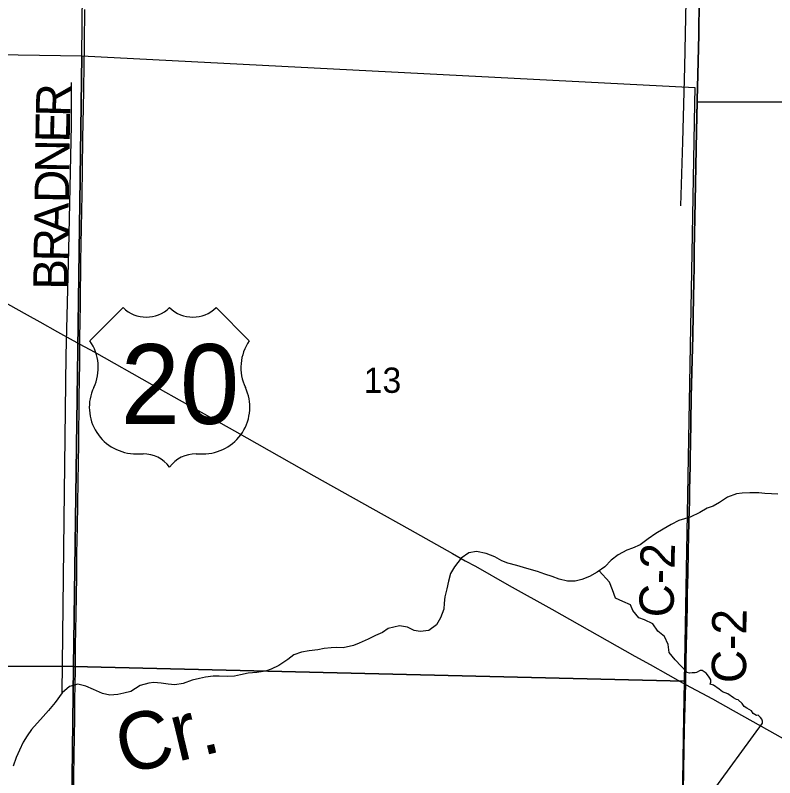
# Model space of a CAD drawing. Extents: x 0 to 34, y 0 to 22.
# Drawn here: x 6.42 to 7.676, y 18.874 to 20.135 of the extents above; entities that cross this region are included whole.
import ezdxf

# ---------------------------------------------------------------- set-up
doc = ezdxf.new("R2010")
doc.units = 0
for name, color, linetype in [('GM_X_City_Street', 7, 'Continuous'), ('GM_X_County_Road', 7, 'Continuous'), ('GM_X_County_Road_Text', 7, 'Continuous'), ('GM_X_Major_River', 7, 'Continuous'), ('GM_X_Major_River_Text', 7, 'Continuous'), ('GM_X_Minor_River', 7, 'Continuous'), ('GM_X_Section', 7, 'Continuous'), ('GM_X_Section_Text', 7, 'Continuous'), ('GM_X_Township_Road', 7, 'Continuous'), ('GM_X_Township_Road_Text', 7, 'Continuous'), ('GM_X_US_Location', 7, 'Continuous'), ('GM_X_US_Route', 7, 'Continuous'), ('GM_X_US_Shield', 7, 'Continuous'), ('SH_Cut_Line', 7, 'Continuous')]:
    doc.layers.add(name, color=color, linetype=linetype)

msp = doc.modelspace()

# ---------------------------------------------------------------- linework, layer by layer
at = {"layer": 'GM_X_City_Street'}
msp.add_lwpolyline([(6.5392, 20.9), (5.527, 20.9), (5.5144, 20.0832), (6.5307, 20.0674)], close=True, dxfattribs=at)
at = {"layer": 'GM_X_County_Road'}
for points in [[(7.5482, 19.9914), (7.5483, 19.9933), (7.5491, 20.0362), (7.5506, 20.1015), (7.5514, 20.1605), (7.5521, 20.1904), (7.5528, 20.2173), (7.5543, 20.2911), (7.5548, 20.3278), (7.556, 20.3619), (7.5564, 20.3806), (7.5567, 20.4036), (7.5571, 20.4228), (7.5579, 20.4589), (7.5585, 20.4894), (7.559, 20.516)], [(7.5287, 19.0281), (7.5295, 19.0663), (7.5299, 19.0908), (7.5305, 19.1119), (7.5312, 19.1349), (7.5315, 19.1554), (7.5318, 19.1772), (7.5324, 19.2101), (7.5332, 19.2474), (7.5337, 19.2735), (7.5342, 19.2944), (7.5347, 19.3177), (7.5351, 19.327), (7.5353, 19.3363), (7.5355, 19.3489), (7.5362, 19.3891), (7.5364, 19.4034), (7.5368, 19.4258), (7.5377, 19.4606), (7.5385, 19.5035), (7.5394, 19.5445), (7.5407, 19.6035), (7.5417, 19.639), (7.5426, 19.6937), (7.543, 19.7167), (7.5433, 19.7453), (7.5435, 19.772), (7.5448, 19.8261), (7.5472, 19.9423), (7.5482, 19.9914)]]:
    msp.add_lwpolyline(points, dxfattribs=at)
at = {"layer": 'GM_X_Major_River'}
for points in [[(7.6813, 19.3427), (7.6707, 19.3431), (7.6597, 19.344), (7.6499, 19.3448), (7.6351, 19.3449), (7.6222, 19.3442), (7.6127, 19.3432), (7.5982, 19.338), (7.5845, 19.329), (7.5742, 19.3226), (7.5643, 19.3193), (7.5521, 19.3122), (7.536, 19.3044)], [(7.536, 19.3044), (7.5177, 19.299), (7.5047, 19.2924), (7.4916, 19.2848), (7.4797, 19.2775), (7.467, 19.2691), (7.4538, 19.2591), (7.4412, 19.2534), (7.4313, 19.2502), (7.4175, 19.2426), (7.4055, 19.2335), (7.395, 19.2226), (7.3827, 19.2138), (7.37, 19.2065), (7.357, 19.2015), (7.3463, 19.1991), (7.3334, 19.1991), (7.3195, 19.2024), (7.3082, 19.2065), (7.2962, 19.2106), (7.2838, 19.2151), (7.2703, 19.2188), (7.2605, 19.2213), (7.2496, 19.2246), (7.235, 19.2288), (7.2248, 19.2324), (7.2132, 19.2392), (7.199, 19.2444), (7.1828, 19.2479), (7.1702, 19.2455), (7.1575, 19.2371), (7.1469, 19.2226), (7.1402, 19.2113), (7.1365, 19.1989), (7.1339, 19.1861), (7.1309, 19.1728), (7.1295, 19.1626), (7.1289, 19.1528), (7.1233, 19.1385), (7.1169, 19.1269), (7.1042, 19.1173), (7.0901, 19.1154), (7.0799, 19.1172), (7.0691, 19.1227), (7.0555, 19.125), (7.0372, 19.1205), (7.0276, 19.1142), (7.0161, 19.1088), (7.004, 19.1028), (6.9893, 19.0966), (6.9797, 19.0926), (6.9626, 19.0889), (6.952, 19.0891), (6.9425, 19.0886), (6.9311, 19.0874), (6.9209, 19.0853), (6.9064, 19.0834), (6.8939, 19.0814), (6.8813, 19.0768), (6.8709, 19.0695), (6.8562, 19.0596), (6.8437, 19.0532), (6.834, 19.0503), (6.8196, 19.0479), (6.8055, 19.0468), (6.7926, 19.0441), (6.7827, 19.042), (6.7713, 19.0411), (6.7577, 19.0419), (6.7475, 19.0417), (6.7349, 19.0401), (6.725, 19.0381), (6.7128, 19.035), (6.6979, 19.0296), (6.6843, 19.0277), (6.6733, 19.0287), (6.6616, 19.0301), (6.6496, 19.0312), (6.6411, 19.0303), (6.627, 19.0264), (6.6116, 19.0166), (6.5998, 19.0138), (6.5899, 19.0114), (6.577, 19.0106), (6.5646, 19.0131), (6.5496, 19.0196), (6.5373, 19.0252), (6.5241, 19.0286), (6.51, 19.0247), (6.4982, 19.0142), (6.4862, 18.9984), (6.4753, 18.985), (6.4667, 18.9753), (6.4472, 18.9538), (6.4402, 18.9433), (6.4335, 18.9328), (6.4275, 18.9197), (6.4222, 18.9073), (6.417, 18.893)]]:
    msp.add_lwpolyline(points, dxfattribs=at)
at = {"layer": 'GM_X_Minor_River'}
msp.add_line((7.5282, 18.7894), (7.656, 18.9638), dxfattribs=at)
for points in [[(7.5437, 20.9), (7.5419, 20.8536), (7.5371, 20.7342), (7.5355, 20.6109), (7.5328, 20.4994), (7.5329, 20.3973), (7.5305, 20.3017), (7.5295, 20.186), (7.5269, 20.0494), (7.5234, 19.925), (7.5204, 19.8192)], [(6.4982, 19.0142), (6.5013, 19.3001), (6.5046, 19.5721), (6.5093, 19.7466), (6.5137, 19.9529), (6.5136, 20.0231)], [(7.5312, 19.0481), (7.5116, 19.0687), (7.5013, 19.0811), (7.5001, 19.0941), (7.494, 19.1071), (7.4829, 19.1161), (7.4745, 19.1285), (7.461, 19.1349), (7.4512, 19.1385), (7.4417, 19.1501), (7.4374, 19.1597), (7.425, 19.165), (7.4126, 19.1709), (7.4077, 19.1847), (7.4027, 19.1974), (7.386, 19.2162)], [(7.656, 18.9638), (7.6559, 18.9645), (7.6559, 18.9676), (7.6548, 18.9706), (7.6526, 18.9733), (7.6489, 18.9772), (7.6462, 18.9768), (7.6432, 18.9784), (7.6406, 18.9803), (7.6376, 18.9845), (7.6301, 18.9888), (7.6256, 18.9919), (7.6223, 18.9965), (7.6159, 19.0026), (7.6129, 19.0034), (7.608, 19.0061), (7.5983, 19.0123), (7.5896, 19.0159), (7.587, 19.0182), (7.584, 19.0205), (7.5747, 19.0267), (7.5694, 19.0286), (7.5706, 19.0321), (7.5702, 19.0355), (7.5688, 19.0385), (7.5665, 19.0416), (7.5628, 19.0469), (7.5561, 19.0512), (7.5527, 19.0513), (7.5468, 19.0479), (7.5444, 19.0475), (7.5397, 19.0475), (7.5349, 19.047), (7.5312, 19.0481)]]:
    msp.add_lwpolyline(points, dxfattribs=at)
at = {"layer": 'GM_X_Section'}
for points in [[(6.5307, 20.0674), (6.5168, 19.0579), (5.5091, 19.0615), (5.5144, 20.0832)], [(7.544, 20.0152), (7.5437, 19.988), (7.5264, 19.0334), (6.5168, 19.0579), (6.5307, 20.0674)], [(6.5168, 19.0579), (6.5049, 18.0487), (5.5052, 18.0545), (5.5091, 19.0615)], [(7.5264, 19.0334), (7.5252, 18.9738), (7.5101, 18.0247), (6.5049, 18.0487), (6.5168, 19.0579)]]:
    msp.add_lwpolyline(points, close=True, dxfattribs=at)
at = {"layer": 'GM_X_Township_Road'}
msp.add_line((7.5482, 19.9914), (8.4697, 19.9905), dxfattribs=at)
for points in [[(6.5273, 19.5908), (6.5272, 19.6021), (6.5272, 19.6059), (6.5275, 19.6233), (6.5281, 19.6606), (6.5291, 19.7277), (6.5295, 19.7557), (6.5309, 19.8384), (6.5315, 19.8788), (6.5324, 19.9317), (6.533, 19.9553), (6.5338, 20.0094), (6.5346, 20.0535), (6.5347, 20.0809), (6.535, 20.0889), (6.5357, 20.1441)], [(6.5168, 18.8264), (6.5175, 18.8743), (6.5181, 18.9128), (6.5186, 18.9394), (6.519, 18.9744), (6.5191, 18.9974), (6.5197, 19.0322), (6.5198, 19.0465), (6.5199, 19.0657), (6.5203, 19.0912), (6.5207, 19.1192), (6.5211, 19.1422), (6.5216, 19.1758), (6.5221, 19.2062), (6.5225, 19.2448), (6.5233, 19.2889), (6.5243, 19.3635), (6.5255, 19.4252), (6.5261, 19.5034), (6.5272, 19.5594), (6.5274, 19.5737), (6.5273, 19.5908)]]:
    msp.add_lwpolyline(points, dxfattribs=at)
at = {"layer": 'GM_X_US_Route'}
for points in [[(7.5511, 20.1611), (7.5504, 20.102), (7.5489, 20.0368), (7.548, 19.9939), (7.548, 19.992), (7.547, 19.9429), (7.5446, 19.8266), (7.5433, 19.7726), (7.543, 19.7458), (7.5428, 19.7172), (7.5424, 19.6942), (7.5415, 19.6395), (7.5405, 19.6041), (7.5392, 19.545), (7.5382, 19.504), (7.5374, 19.4611), (7.5366, 19.4263), (7.5362, 19.4039), (7.536, 19.3896), (7.5353, 19.3494), (7.5351, 19.3368), (7.5349, 19.3275), (7.5344, 19.3182), (7.534, 19.295), (7.5334, 19.2741), (7.5329, 19.248), (7.5322, 19.2107), (7.5315, 19.1778), (7.5313, 19.156), (7.531, 19.1355), (7.5303, 19.1125), (7.5297, 19.0914), (7.5293, 19.0669), (7.5285, 19.0287), (7.5263, 18.9541), (7.5247, 18.8516)], [(7.5247, 18.8516), (7.5263, 18.9541), (7.5285, 19.0287), (7.5293, 19.0669), (7.5297, 19.0914), (7.5303, 19.1125), (7.531, 19.1355), (7.5313, 19.156), (7.5315, 19.1778), (7.5322, 19.2107), (7.5329, 19.248), (7.5334, 19.2741), (7.534, 19.295), (7.5344, 19.3182), (7.5349, 19.3275), (7.5351, 19.3368), (7.5353, 19.3494), (7.536, 19.3896), (7.5362, 19.4039), (7.5366, 19.4263), (7.5374, 19.4611), (7.5382, 19.504), (7.5392, 19.545), (7.5405, 19.6041), (7.5415, 19.6395), (7.5424, 19.6942), (7.5428, 19.7172), (7.543, 19.7458), (7.5433, 19.7726), (7.5446, 19.8266), (7.547, 19.9429), (7.548, 19.992), (7.548, 19.9939), (7.5489, 20.0368), (7.5504, 20.102), (7.5511, 20.1611)], [(6.3074, 19.7131), (6.3421, 19.6939), (6.4402, 19.6394), (6.4611, 19.6277), (6.4904, 19.6113), (6.5273, 19.5908)], [(6.5273, 19.5908), (6.5508, 19.5778), (6.6461, 19.524), (6.7051, 19.4907), (6.7827, 19.4473), (6.9143, 19.3731), (7.0118, 19.3182), (7.0727, 19.2843), (7.1431, 19.2445), (7.1644, 19.2327), (7.1811, 19.2234), (7.2369, 19.1919), (7.3073, 19.1523), (7.4447, 19.075)], [(7.4447, 19.075), (7.4699, 19.0609), (7.5287, 19.0281)], [(7.5249, 18.851), (7.5266, 18.9536), (7.5287, 19.0281)], [(7.5287, 19.0281), (7.5732, 19.0042), (7.6072, 18.9851)], [(7.6072, 18.9851), (7.6673, 18.9512), (7.8132, 18.8691), (8.0488, 18.7365), (8.4602, 18.5051), (8.5129, 18.4758), (8.6254, 18.4131), (8.7327, 18.353), (8.8455, 18.2902), (8.9, 18.2599)]]:
    msp.add_lwpolyline(points, dxfattribs=at)
at = {"layer": 'GM_X_US_Shield'}
for p, q in [((6.5987, 19.6512), (6.5438, 19.5962)), ((6.8074, 19.5962), (6.7525, 19.6512)), ((6.6207, 19.4095), (6.6317, 19.4095)), ((6.7195, 19.4095), (6.7305, 19.4095))]:
    msp.add_line(p, q, dxfattribs=at)
for centre, radius, start, end in [((6.6371, 19.6904), 0.0549, 225.573, 314.427), ((6.7141, 19.6904), 0.0549, 225.573, 314.427), ((6.4808, 19.5521), 0.0769, 334.5471, 35.0009), ((6.8704, 19.5521), 0.0769, 144.9991, 205.4529), ((6.6198, 19.4864), 0.0769, 154.8319, 270.6383), ((6.7314, 19.4864), 0.0769, 269.3617, 25.1681), ((6.6317, 19.3545), 0.0549, 36.8699, 90), ((6.7195, 19.3545), 0.0549, 90, 143.1301)]:
    msp.add_arc(centre, radius, start, end, dxfattribs=at)
at = {"layer": 'SH_Cut_Line'}
for points in [[(7.5247, 18.8516), (7.5263, 18.9541), (7.5285, 19.0287), (7.5293, 19.0669), (7.5297, 19.0914), (7.5303, 19.1125), (7.531, 19.1355), (7.5313, 19.156), (7.5315, 19.1778), (7.5322, 19.2107), (7.5329, 19.248), (7.5334, 19.2741), (7.534, 19.295), (7.5344, 19.3182), (7.5349, 19.3275), (7.5351, 19.3368), (7.5353, 19.3494), (7.536, 19.3896), (7.5362, 19.4039), (7.5366, 19.4263), (7.5374, 19.4611), (7.5382, 19.504), (7.5392, 19.545), (7.5405, 19.6041), (7.5415, 19.6395), (7.5424, 19.6942), (7.5428, 19.7172), (7.543, 19.7458), (7.5433, 19.7726), (7.5446, 19.8266), (7.547, 19.9429), (7.548, 19.992), (7.548, 19.9939), (7.5489, 20.0368), (7.5504, 20.102), (7.5511, 20.1611)], [(7.5511, 20.1611), (7.5504, 20.102), (7.5489, 20.0368), (7.548, 19.9939), (7.548, 19.992), (7.547, 19.9429), (7.5446, 19.8266), (7.5433, 19.7726), (7.543, 19.7458), (7.5428, 19.7172), (7.5424, 19.6942), (7.5415, 19.6395), (7.5405, 19.6041), (7.5392, 19.545), (7.5382, 19.504), (7.5374, 19.4611), (7.5366, 19.4263), (7.5362, 19.4039), (7.536, 19.3896), (7.5353, 19.3494), (7.5351, 19.3368), (7.5349, 19.3275), (7.5344, 19.3182), (7.534, 19.295), (7.5334, 19.2741), (7.5329, 19.248), (7.5322, 19.2107), (7.5315, 19.1778), (7.5313, 19.156), (7.531, 19.1355), (7.5303, 19.1125), (7.5297, 19.0914), (7.5293, 19.0669), (7.5285, 19.0287), (7.5263, 18.9541), (7.5247, 18.8516)]]:
    msp.add_lwpolyline(points, dxfattribs=at)

# ---------------------------------------------------------------- texts
at = {"layer": 'GM_X_County_Road_Text'}
for rotation, p in [(88.8114, (7.5087, 19.1386)), (89.5436, (7.6286, 19.0301))]:
    msp.add_text('C-2', height=0.05682, rotation=rotation, dxfattribs=at).set_placement(p)
at = {"layer": 'GM_X_Major_River_Text'}
msp.add_text('Cr.', height=0.09475, rotation=13.4423, dxfattribs=at).set_placement((6.5996, 18.8789))
at = {"layer": 'GM_X_Section_Text'}
msp.add_text('13', height=0.04186, rotation=0, dxfattribs=at).set_placement((6.9964, 19.5102))
at = {"layer": 'GM_X_Township_Road_Text'}
for s, rotation, p in [('R', 88.5635, (6.5111, 19.9661)), ('E', 89.1214, (6.5105, 19.9238)), ('N', 89.1293, (6.5097, 19.8738)), ('D', 89.1293, (6.509, 19.8238)), ('A', 89.131, (6.5082, 19.7738)), ('R', 89.1296, (6.5075, 19.7271)), ('B', 89.1296, (6.5068, 19.6805))]:
    msp.add_text(s, height=0.0568, rotation=rotation, dxfattribs=at).set_placement(p)
at = {"layer": 'GM_X_US_Location'}
for s in ['0', '/']:
    msp.add_text(s, height=0.000189, dxfattribs=at).set_placement((6.6755, 19.5238))
msp.add_text('20', height=0.000189, rotation=0, dxfattribs=at).set_placement((6.6364, 19.4846))
at = {"layer": 'GM_X_US_Shield'}
msp.add_text('20', height=0.13184, dxfattribs=at).set_placement((6.5947, 19.4589))

doc.saveas('drawing.dxf')
